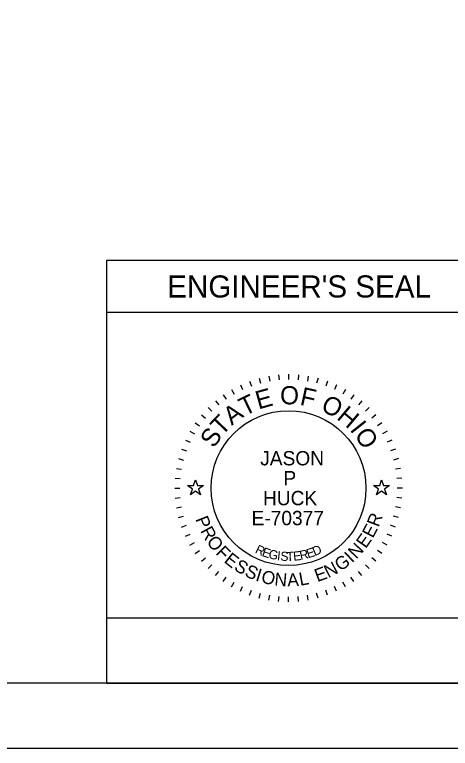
# Model space of a CAD drawing. Extents: x 6.3 to 40.3, y 9 to 31.
# Drawn here: x 12.99 to 16.34, y 9.05 to 14.68 of the extents above; entities that cross this region are included whole.
import ezdxf

# ---------------------------------------------------------------- set-up
doc = ezdxf.new("R2010")
doc.units = 0
for name, color, linetype in [('SH_Border', 7, 'Continuous'), ('SH_Cut_Line', 7, 'Continuous'), ('SH_Data', 7, 'Continuous'), ('SH_Seal', 7, 'Continuous')]:
    doc.layers.add(name, color=color, linetype=linetype)

msp = doc.modelspace()

# ---------------------------------------------------------------- linework, layer by layer
at = {"layer": 'SH_Border'}
msp.add_lwpolyline([(7.8446, 30.5457), (39.8446, 30.5457), (39.8446, 9.5457), (7.8446, 9.5457)], close=True, dxfattribs=at)
at = {"layer": 'SH_Cut_Line'}
msp.add_lwpolyline([(6.3446, 9.0457), (40.3446, 9.0457), (40.3446, 31.0457), (6.3446, 31.0457)], close=True, dxfattribs=at)
at = {"layer": 'SH_Data'}
for p, q in [((16.4946, 12.7957), (13.6946, 12.7957)), ((13.6946, 12.7957), (13.6946, 9.5457)), ((16.4946, 12.3957), (13.6946, 12.3957)), ((16.4946, 9.5457), (13.6946, 9.5457))]:
    msp.add_line(p, q, dxfattribs=at)
msp.add_lwpolyline([(16.4946, 9.5457), (16.4946, 10.0457), (13.6946, 10.0457), (13.6946, 9.5457)], close=True, dxfattribs=at)
at = {"layer": 'SH_Seal'}
for p, q in [((14.9427, 11.9074), (14.9496, 11.868)), ((15.0183, 11.9174), (15.0218, 11.8775)), ((15.0946, 11.9207), (15.0946, 11.8807)), ((15.1709, 11.9174), (15.1674, 11.8775)), ((15.2465, 11.9074), (15.2396, 11.868)), ((14.7953, 11.868), (14.809, 11.8304)), ((14.8681, 11.8909), (14.8785, 11.8523)), ((15.3211, 11.8909), (15.3107, 11.8523)), ((15.3939, 11.868), (15.3802, 11.8304)), ((14.6571, 11.8035), (14.6771, 11.7689)), ((14.7248, 11.8387), (14.7417, 11.8025)), ((15.4644, 11.8387), (15.4475, 11.8025)), ((15.5321, 11.8035), (15.5121, 11.7689)), ((14.5927, 11.7625), (14.6157, 11.7297)), ((15.5965, 11.7625), (15.5735, 11.7297)), ((14.5322, 11.716), (14.5579, 11.6854)), ((15.657, 11.716), (15.6313, 11.6854)), ((14.4759, 11.6644), (14.5042, 11.6362)), ((15.7133, 11.6644), (15.685, 11.6362)), ((14.4243, 11.6082), (14.455, 11.5825)), ((15.7649, 11.6082), (15.7343, 11.5825)), ((14.3778, 11.5476), (14.4106, 11.5247)), ((15.8114, 11.5476), (15.7786, 11.5247)), ((14.3368, 11.4832), (14.3715, 11.4632)), ((15.8524, 11.4832), (15.8177, 11.4632)), ((14.3016, 11.4155), (14.3378, 11.3986)), ((15.8876, 11.4155), (15.8514, 11.3986)), ((14.2724, 11.345), (14.31, 11.3313)), ((15.9168, 11.345), (15.8792, 11.3313)), ((14.2494, 11.2722), (14.2881, 11.2618)), ((15.9398, 11.2722), (15.9012, 11.2618)), ((14.2329, 11.1977), (14.2723, 11.1907)), ((15.9563, 11.1977), (15.9169, 11.1907)), ((14.2229, 11.122), (14.2628, 11.1185)), ((15.9663, 11.122), (15.9264, 11.1185)), ((14.2196, 11.0457), (14.2596, 11.0457)), ((15.9696, 11.0457), (15.9296, 11.0457)), ((14.2229, 10.9695), (14.2628, 10.9729)), ((15.9663, 10.9695), (15.9264, 10.9729)), ((14.2329, 10.8938), (14.2723, 10.9007)), ((15.9563, 10.8938), (15.9169, 10.9007)), ((14.2494, 10.8193), (14.2881, 10.8296)), ((15.9398, 10.8193), (15.9012, 10.8296)), ((14.2724, 10.7465), (14.31, 10.7601)), ((15.9168, 10.7465), (15.8792, 10.7601)), ((14.3016, 10.6759), (14.3378, 10.6928)), ((15.8876, 10.6759), (15.8514, 10.6928)), ((14.3368, 10.6082), (14.3715, 10.6282)), ((15.8524, 10.6082), (15.8177, 10.6282)), ((14.3778, 10.5438), (14.4106, 10.5668)), ((15.8114, 10.5438), (15.7786, 10.5668)), ((14.4243, 10.4833), (14.455, 10.509)), ((15.7649, 10.4833), (15.7343, 10.509)), ((14.4759, 10.427), (14.5042, 10.4553)), ((15.7133, 10.427), (15.685, 10.4553)), ((14.5322, 10.3754), (14.5579, 10.4061)), ((15.657, 10.3754), (15.6313, 10.4061)), ((14.5927, 10.329), (14.6157, 10.3617)), ((14.6571, 10.288), (14.6771, 10.3226)), ((15.5321, 10.288), (15.5121, 10.3226)), ((15.5965, 10.329), (15.5735, 10.3617)), ((14.7248, 10.2527), (14.7417, 10.289)), ((15.4644, 10.2527), (15.4475, 10.289)), ((14.7953, 10.2235), (14.809, 10.2611)), ((14.8681, 10.2005), (14.8785, 10.2392)), ((14.9427, 10.184), (14.9496, 10.2234)), ((15.0183, 10.1741), (15.0218, 10.2139)), ((15.0946, 10.1707), (15.0946, 10.2107)), ((15.1709, 10.1741), (15.1674, 10.2139)), ((15.2465, 10.184), (15.2396, 10.2234)), ((15.3211, 10.2005), (15.3107, 10.2392)), ((15.3939, 10.2235), (15.3802, 10.2611))]:
    msp.add_line(p, q, dxfattribs=at)
for points in [[(14.3182, 11.0657), (14.3651, 11.0657), (14.3796, 11.1103), (14.3941, 11.0657), (14.441, 11.0657), (14.4031, 11.0381), (14.4176, 10.9935), (14.3796, 11.0211), (14.3416, 10.9935), (14.3561, 11.0381)], [(15.7482, 11.0657), (15.7951, 11.0657), (15.8096, 11.1103), (15.8241, 11.0657), (15.871, 11.0657), (15.8331, 11.0381), (15.8476, 10.9935), (15.8096, 11.0211), (15.7716, 10.9935), (15.7861, 11.0381)]]:
    msp.add_lwpolyline(points, close=True, dxfattribs=at)
msp.add_circle((15.0946, 11.0457), 0.595, dxfattribs=at)

# ---------------------------------------------------------------- texts
at = {"layer": 'SH_Data'}
msp.add_text("ENGINEER'S SEAL", height=0.17, dxfattribs=at).set_placement((14.1622, 12.5107))
at = {"layer": 'SH_Seal'}
for s, height, rotation, p in [('E', 0.14, 15.7571, (14.863, 11.6495)), ('O', 0.14, 359.7812, (15.0293, 11.69)), ('F', 0.14, 347.4362, (15.1757, 11.6875)), ('T', 0.14, 25.7167, (14.7562, 11.5976)), ('O', 0.14, 332.2586, (15.3344, 11.6472)), ('A', 0.14, 36.4747, (14.658, 11.5238)), ('H', 0.14, 319.9136, (15.4578, 11.5818)), ('T', 0.14, 46.4344, (14.5829, 11.4422)), ('I', 0.14, 308.367, (15.5611, 11.494)), ('S', 0.14, 57.1924, (14.5227, 11.3471)), ('O', 0.14, 303.1491, (15.5968, 11.4546)), ('P', 0.1, 291.494, (14.3769, 10.8078)), ('R', 0.1, 69.2322, (15.7865, 10.7411)), ('E', 0.1, 61.9951, (15.7422, 10.6556)), ('R', 0.1, 298.7311, (14.4136, 10.7174)), ('O', 0.1, 306.4666, (14.4601, 10.634)), ('E', 0.1, 54.758, (15.6879, 10.5771)), ('F', 0.1, 314.7068, (14.5289, 10.544)), ('R', 0.07, 334.487, (14.8321, 10.5508)), ('D', 0.07, 23.3052, (15.2956, 10.5227)), ('N', 0.1, 47.0224, (15.6148, 10.4965)), ('E', 0.1, 321.4393, (14.5924, 10.4805)), ('E', 0.07, 341.04, (14.8852, 10.5258)), ('G', 0.07, 347.4752, (14.9361, 10.5075)), ('I', 0.07, 353.7858, (15.0037, 10.4925)), ('S', 0.07, 356.8926, (15.0304, 10.4886)), ('T', 0.07, 3.0061, (15.0803, 10.4844)), ('E', 0.07, 6.0117, (15.1335, 10.4869)), ('R', 0.07, 11.9184, (15.1871, 10.4931)), ('E', 0.07, 17.6836, (15.2444, 10.5059)), ('I', 0.1, 43.287, (15.5815, 10.4671)), ('S', 0.1, 328.6764, (14.6689, 10.421)), ('G', 0.1, 35.0469, (15.4927, 10.4027)), ('S', 0.1, 335.9134, (14.751, 10.3723)), ('E', 0.1, 20.0742, (15.3158, 10.3227)), ('N', 0.1, 27.3113, (15.3991, 10.3532)), ('I', 0.1, 343.1505, (14.8352, 10.3354)), ('O', 0.1, 346.8859, (14.8785, 10.3209)), ('N', 0.1, 355.1261, (14.9834, 10.2975)), ('A', 0.1, 2.8617, (15.0869, 10.2894)), ('L', 0.1, 10.0987, (15.184, 10.2948))]:
    msp.add_text(s, height=height, rotation=rotation, dxfattribs=at).set_placement(p)
for s, p in [('JASON', (14.8767, 11.2206)), ('P', (15.0551, 11.0674)), ('HUCK', (14.8981, 10.9141)), ('E-70377', (14.8105, 10.7608))]:
    msp.add_text(s, height=0.11, dxfattribs=at).set_placement(p)

doc.saveas('drawing.dxf')
